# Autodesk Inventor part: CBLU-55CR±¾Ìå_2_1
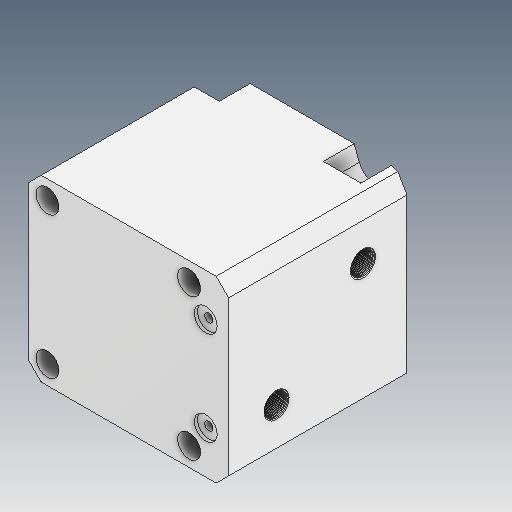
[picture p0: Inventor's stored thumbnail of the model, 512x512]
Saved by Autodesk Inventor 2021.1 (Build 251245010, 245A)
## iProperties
Created: 2021-05
Part Number: CBLU-55CR±¾Ìå_2_1
Material: Ogólny
Document SubType Name: Modeling
Designer: user
Density: 1 g/cm^3
Appearance: Domyślna
Author: user
Revision Number: ÈÎºÎ
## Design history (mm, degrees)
feature "ÊäÈë1"
feature "ÊäÈë2"
feature "ÇÐ³ý-À­Éì1" [ÊäÈë]
node "Bryła1"
node "Bryła2"
node "Bryła3"
